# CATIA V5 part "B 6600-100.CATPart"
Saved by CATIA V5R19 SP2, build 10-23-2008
Part number: B 6600-100
Bounding box of the stored display mesh (mm): x -59.975 to 59.975, y -59.975 to 59.975, z 0 to 340
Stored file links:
  C:\Users\Bora\Desktop\3D Katı model\B serisi\B 6600\B 6600-100.CATPart
  C:\Program Files\Dassault Systemes\B19\intel_a\reffiles\standard\MetricThickPitch.txt
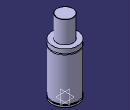
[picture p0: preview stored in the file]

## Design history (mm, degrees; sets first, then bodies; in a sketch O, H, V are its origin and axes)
Body1 (main body)
  Sketch1 on yz-plane, origin (0, 0, 0), H (0, 1, 0), V (0, 0, 1)
    point P3 (37.5, 339)
    point P5 (37.5, 339)
    point P10 (60, 212)
    point P11 (60, 217)
    point P13 (60, 217)
    point P14 (60, 212)
    line L1 (60, 0) -> (60, 8)
    line L2 (37.5, 339) -> (37.5, 237)
    arc A1 centre (36.5, 339) radius 1 from (37.5, 339) to (36.5, 340) ccw
    line L3 (56, 13) -> (56, 8)
    line L4 (60, 13) -> (60, 212)
    line L5 (60, 217) -> (60, 237)
    arc A2 centre (60, 214.5) radius 2.5 from (60, 217) to (60, 212) ccw
    line L6 (36.5, 340) -> (0, 340)
    point P15 (0, 340)
    line L7 (37.5, 237) -> (60, 237)
    line L8 (0, 0) -> (60, 0)
    line L9 (56, 13) -> (60, 13)
    line L10 (56, 8) -> (60, 8)
    coincidence: P15 V, P3 P5, P10 P14, P11 P13
    tangency: L6 A1
    horizontal: L7 H, L8 H, L9 H, L10 H
  Shaft1: profile Sketch1, axis Sketch1.V, angle 360
  Sketch2 on face of Shaft1 from Sketch1.L8, origin (0, 0, 0), H (1, 0, 0), V (0, -1, 0)
    point P1 (40, 0)
    distance P1 V = 40
  Hole1: placed by Sketch2, at (40, 0, 0) direction (0, 0, 1), diameter 8.376, depth 16, threaded "M10", thread diameter 10, thread depth 16, pitch 1.5
  CircPattern1: of Hole1, instances 4, angular step 90, axis from xy-plane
